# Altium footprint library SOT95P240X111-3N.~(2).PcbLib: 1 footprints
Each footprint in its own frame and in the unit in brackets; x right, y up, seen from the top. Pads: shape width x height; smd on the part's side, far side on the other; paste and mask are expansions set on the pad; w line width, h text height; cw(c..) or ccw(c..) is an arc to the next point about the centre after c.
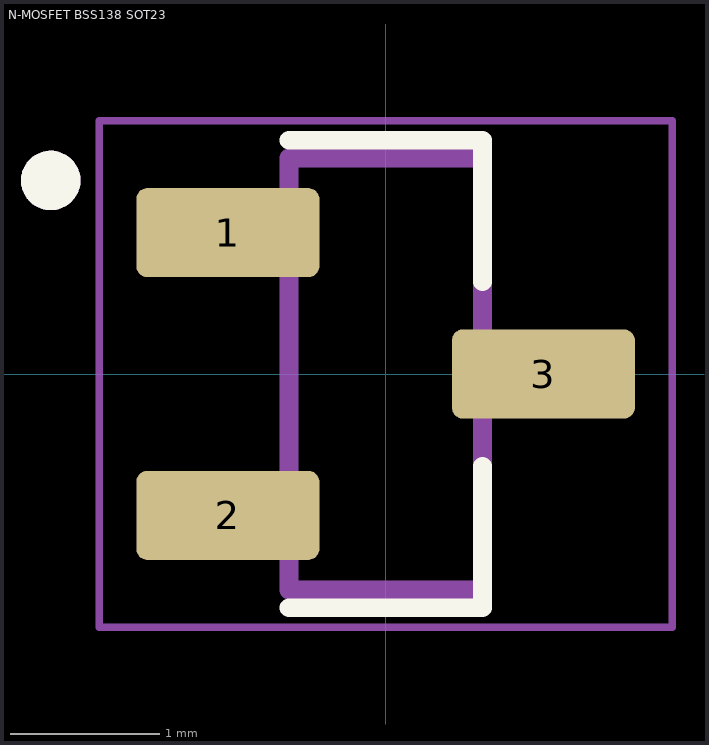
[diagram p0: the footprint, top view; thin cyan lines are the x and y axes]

## N-MOSFET BSS138 SOT23 [mm] "N-MOSFET BSS138 SOT23 SOT95P240X111-3N"
height 1.11
pads (3):
  rrect25% 1.23x0.6 smd: 1(-1.06,0.95) 2(-1.06,-0.95) 3(1.06,0)
Top Overlay:
  circle w0.2: c-2.25,1.3 r0.1
  lines w0.127: -0.65,-1.57 0.65,-1.57 0.65,-0.62 ; -0.65,1.57 0.65,1.57 0.65,0.62
Assembly Top:
  circle w0.2: c-2.25,1.3 r0.1
  lines w0.127: -0.65,-1.45 0.65,-1.45 0.65,1.45 -0.65,1.45 -0.65,-1.45
Courtyard Top:
  lines w0.05: -1.925,-1.7 -1.925,1.7 1.925,1.7 1.925,-1.7 -1.925,-1.7
3D body "step_temp.STEP": height 1.11, standoff 0, extent -1.2,-1.45 1.2,1.45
